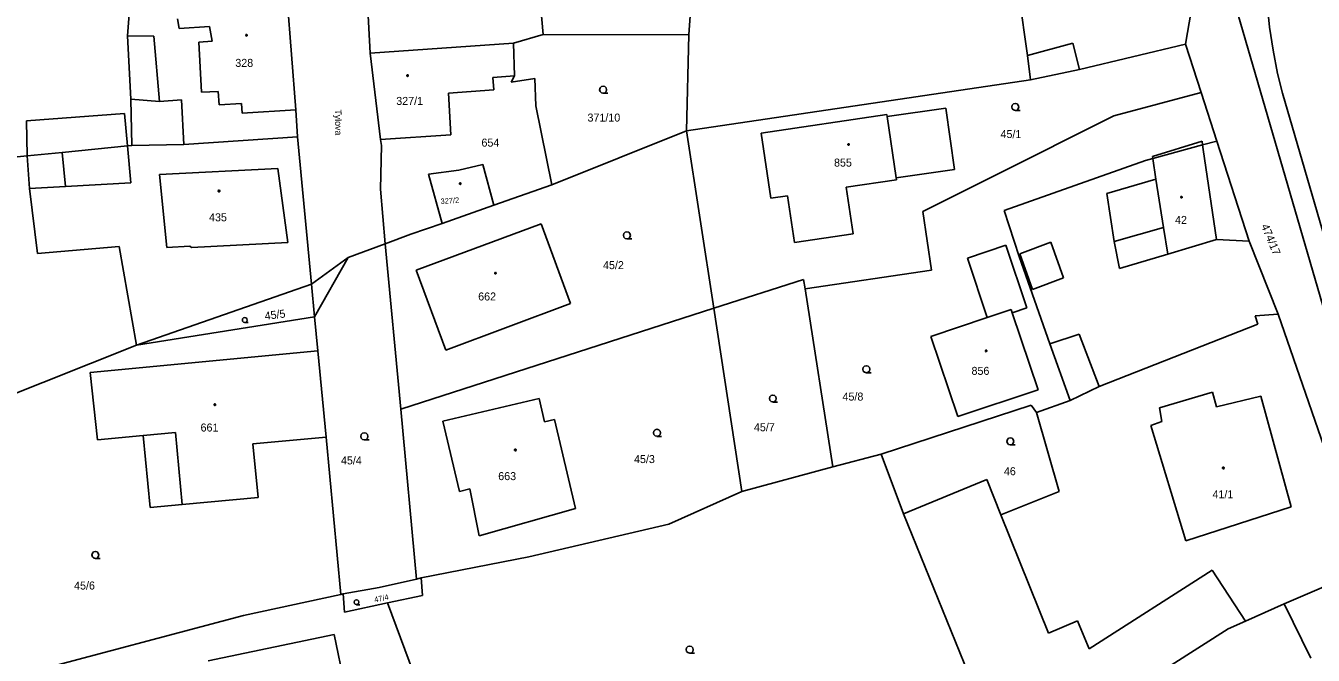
# Model space of a CAD drawing. Extents: x -757994 to -755874, y -1047691 to -1046119.
# Drawn here: x -757584.9 to -757448.1, y -1046980.7 to -1046913.8 of the extents above; entities that cross this region are included whole.
import ezdxf

# ---------------------------------------------------------------- set-up
doc = ezdxf.new("R2010")
doc.units = 0
doc.layers.add('katastrální mapa', color=7, linetype='Continuous')

msp = doc.modelspace()

# ---------------------------------------------------------------- linework, layer by layer
at = {"layer": 'katastrální mapa'}
for p, q in [((-757478.46, -1046916.96), (-757481.16, -1046897.98)), ((-757548.94, -1046903.57), (-757548.29, -1046916.7)), ((-757529.91, -1046914.73), (-757530.85, -1046904.01)), ((-757514.43, -1046914.75), (-757513.9, -1046906.58)), ((-757556.16, -1046922.73), (-757557.11, -1046910.95)), ((-757573.81, -1046911.65), (-757574.05, -1046914.86)), ((-757461.69, -1046915.73), (-757461.11, -1046912.25)), ((-757456.38, -1046911.66), (-757436.98, -1046978.47)), ((-757568.73, -1046913.04), (-757568.55, -1046914.08)), ((-757568.55, -1046914.08), (-757565.34, -1046913.88)), ((-757565.34, -1046913.88), (-757565.06, -1046915.43)), ((-757574.05, -1046914.86), (-757573.7, -1046921.6)), ((-757571.25, -1046914.89), (-757574.05, -1046914.86)), ((-757570.66, -1046921.83), (-757571.25, -1046914.89)), ((-757565.06, -1046915.43), (-757566.49, -1046915.53)), ((-757566.49, -1046915.53), (-757566.18, -1046920.86)), ((-757533.05, -1046915.64), (-757529.91, -1046914.73)), ((-757514.43, -1046914.75), (-757529.91, -1046914.73)), ((-757514.69, -1046924.95), (-757514.43, -1046914.75)), ((-757473.66, -1046915.63), (-757478.46, -1046916.96)), ((-757472.94, -1046918.43), (-757473.66, -1046915.63)), ((-757548.29, -1046916.7), (-757533.05, -1046915.64)), ((-757548.29, -1046916.7), (-757547.17, -1046925.88)), ((-757532.96, -1046919.12), (-757533.05, -1046915.64)), ((-757478.17, -1046919.55), (-757478.46, -1046916.96)), ((-757472.94, -1046918.43), (-757461.69, -1046915.73)), ((-757460.02, -1046920.89), (-757461.69, -1046915.73)), ((-757535.24, -1046919.29), (-757532.96, -1046919.12)), ((-757535.14, -1046920.58), (-757535.24, -1046919.29)), ((-757532.96, -1046919.12), (-757533.3, -1046919.8)), ((-757530.8, -1046919.4), (-757533.3, -1046919.8)), ((-757530.7, -1046922.3), (-757530.8, -1046919.4)), ((-757514.69, -1046924.95), (-757478.17, -1046919.55)), ((-757478.17, -1046919.55), (-757472.94, -1046918.43)), ((-757566.18, -1046920.86), (-757564.42, -1046920.76)), ((-757564.42, -1046920.76), (-757564.33, -1046922.2)), ((-757539.95, -1046920.96), (-757535.14, -1046920.58)), ((-757539.71, -1046925.36), (-757539.95, -1046920.96)), ((-757469.29, -1046923.35), (-757460.02, -1046920.89)), ((-757458.36, -1046926.04), (-757460.02, -1046920.89)), ((-757451.4, -1046920.95), (-757445.34, -1046941.72)), ((-757573.7, -1046921.6), (-757573.58, -1046926.51)), ((-757570.66, -1046921.83), (-757573.7, -1046921.6)), ((-757568.3, -1046921.65), (-757570.66, -1046921.83)), ((-757568.05, -1046926.41), (-757568.3, -1046921.65)), ((-757564.33, -1046922.2), (-757561.94, -1046922.06)), ((-757561.94, -1046922.06), (-757561.88, -1046923.07)), ((-757529, -1046930.7), (-757530.7, -1046922.3)), ((-757584.79, -1046923.88), (-757574.38, -1046923.1)), ((-757574.38, -1046923.1), (-757574.05, -1046926.56)), ((-757561.88, -1046923.07), (-757556.16, -1046922.73)), ((-757555.99, -1046925.6), (-757556.16, -1046922.73)), ((-757506.76, -1046925.19), (-757493.41, -1046923.22)), ((-757493.41, -1046923.22), (-757493.38, -1046923.42)), ((-757493.38, -1046923.42), (-757487.14, -1046922.54)), ((-757492.41, -1046929.96), (-757493.38, -1046923.42)), ((-757487.14, -1046922.54), (-757486.22, -1046929.05)), ((-757482.1, -1046929.77), (-757469.29, -1046923.35)), ((-757584.72, -1046927.61), (-757584.79, -1046923.88)), ((-757529, -1046930.7), (-757514.69, -1046924.95)), ((-757514.69, -1046924.95), (-757511.78, -1046943.8)), ((-757505.74, -1046932.11), (-757506.76, -1046925.19)), ((-757580.99, -1046927.24), (-757574.05, -1046926.56)), ((-757574.05, -1046926.56), (-757573.58, -1046926.51)), ((-757574.05, -1046926.56), (-757573.68, -1046930.47)), ((-757573.58, -1046926.51), (-757568.05, -1046926.41)), ((-757568.05, -1046926.41), (-757555.99, -1046925.6)), ((-757554.51, -1046941.24), (-757555.99, -1046925.6)), ((-757547.17, -1046925.88), (-757539.71, -1046925.36)), ((-757547.17, -1046925.88), (-757547.09, -1046926.5)), ((-757547.09, -1046926.5), (-757547.17, -1046931.13)), ((-757465.21, -1046927.68), (-757459.94, -1046926.04)), ((-757459.88, -1046926.45), (-757465.18, -1046927.9)), ((-757459.88, -1046926.45), (-757459.94, -1046926.04)), ((-757458.36, -1046926.04), (-757459.88, -1046926.45)), ((-757459.81, -1046926.93), (-757459.88, -1046926.45)), ((-757454.92, -1046936.66), (-757458.36, -1046926.04)), ((-757603.26, -1046929.43), (-757584.72, -1046927.61)), ((-757584.72, -1046927.61), (-757580.99, -1046927.24)), ((-757584.45, -1046931.08), (-757584.72, -1046927.61)), ((-757580.64, -1046930.86), (-757580.99, -1046927.24)), ((-757465.18, -1046927.9), (-757465.94, -1046928.11)), ((-757465.18, -1046927.9), (-757465.21, -1046927.68)), ((-757464.85, -1046930.08), (-757465.18, -1046927.9)), ((-757458.4, -1046936.49), (-757459.81, -1046926.93)), ((-757570.65, -1046929.59), (-757558.07, -1046928.94)), ((-757558.07, -1046928.94), (-757557.02, -1046936.81)), ((-757542.08, -1046929.56), (-757538.86, -1046929.13)), ((-757538.86, -1046929.13), (-757536.33, -1046928.52)), ((-757536.33, -1046928.52), (-757535.15, -1046932.85)), ((-757486.22, -1046929.05), (-757492.41, -1046929.96)), ((-757465.94, -1046928.11), (-757480.97, -1046933.4)), ((-757573.68, -1046930.47), (-757580.64, -1046930.86)), ((-757569.89, -1046937.33), (-757570.65, -1046929.59)), ((-757540.65, -1046934.78), (-757542.08, -1046929.56)), ((-757492.38, -1046930.16), (-757497.72, -1046930.94)), ((-757492.41, -1046929.96), (-757492.38, -1046930.16)), ((-757489.58, -1046933.52), (-757482.1, -1046929.77)), ((-757470.06, -1046931.62), (-757464.85, -1046930.08)), ((-757464.03, -1046935.23), (-757464.85, -1046930.08)), ((-757580.64, -1046930.86), (-757584.45, -1046931.08)), ((-757583.62, -1046937.99), (-757584.45, -1046931.08)), ((-757547.17, -1046931.13), (-757546.67, -1046936.95)), ((-757535.15, -1046932.85), (-757529, -1046930.7)), ((-757503.95, -1046931.85), (-757505.74, -1046932.11)), ((-757503.21, -1046936.8), (-757503.95, -1046931.85)), ((-757497.72, -1046930.94), (-757497, -1046935.89)), ((-757469.26, -1046936.72), (-757470.06, -1046931.62)), ((-757535.15, -1046932.85), (-757540.65, -1046934.78)), ((-757480.97, -1046933.4), (-757479.37, -1046938.3)), ((-757488.66, -1046939.74), (-757489.58, -1046933.52)), ((-757546.67, -1046936.95), (-757543.97, -1046935.94)), ((-757540.65, -1046934.78), (-757543.97, -1046935.94)), ((-757530.11, -1046934.84), (-757543.39, -1046939.74)), ((-757530.11, -1046934.84), (-757526.99, -1046943.3)), ((-757497, -1046935.89), (-757503.21, -1046936.8)), ((-757464.03, -1046935.23), (-757469.26, -1046936.72)), ((-757463.58, -1046938.05), (-757464.03, -1046935.23)), ((-757574.93, -1046937.25), (-757583.62, -1046937.99)), ((-757573.1, -1046947.7), (-757574.93, -1046937.25)), ((-757567.44, -1046937.19), (-757569.89, -1046937.33)), ((-757567.24, -1046937.36), (-757567.44, -1046937.19)), ((-757557.02, -1046936.81), (-757567.24, -1046937.36)), ((-757550.6, -1046938.42), (-757546.67, -1046936.95)), ((-757546.67, -1046936.95), (-757545.03, -1046954.51)), ((-757480.78, -1046937.08), (-757484.86, -1046938.46)), ((-757478.56, -1046943.75), (-757480.78, -1046937.08)), ((-757479.3, -1046938.03), (-757475.99, -1046936.79)), ((-757475.99, -1046936.79), (-757474.66, -1046940.56)), ((-757469.26, -1046936.72), (-757468.72, -1046939.58)), ((-757458.4, -1046936.49), (-757463.58, -1046938.05)), ((-757454.92, -1046936.66), (-757458.4, -1046936.49)), ((-757451.87, -1046944.44), (-757454.92, -1046936.66)), ((-757554.51, -1046941.24), (-757550.6, -1046938.42)), ((-757554.18, -1046944.69), (-757550.6, -1046938.42)), ((-757484.86, -1046938.46), (-757482.76, -1046944.78)), ((-757476.12, -1046947.58), (-757479.37, -1046938.3)), ((-757477.93, -1046941.81), (-757479.3, -1046938.03)), ((-757468.72, -1046939.58), (-757463.58, -1046938.05)), ((-757543.39, -1046939.74), (-757540.26, -1046948.23)), ((-757502.1, -1046941.73), (-757488.66, -1046939.74)), ((-757573.1, -1046947.7), (-757554.51, -1046941.24)), ((-757554.18, -1046944.69), (-757554.51, -1046941.24)), ((-757511.78, -1046943.8), (-757502.25, -1046940.74)), ((-757502.25, -1046940.74), (-757502.1, -1046941.73)), ((-757474.66, -1046940.56), (-757477.93, -1046941.81)), ((-757502.1, -1046941.73), (-757499.15, -1046960.65)), ((-757511.78, -1046943.8), (-757545.03, -1046954.51)), ((-757526.99, -1046943.3), (-757540.26, -1046948.23)), ((-757511.78, -1046943.8), (-757508.8, -1046963.25)), ((-757482.76, -1046944.78), (-757480.22, -1046943.92)), ((-757480.22, -1046943.92), (-757480.1, -1046944.27)), ((-757480.1, -1046944.27), (-757478.56, -1046943.75)), ((-757477.35, -1046952.47), (-757480.1, -1046944.27)), ((-757573.1, -1046947.7), (-757554.18, -1046944.69)), ((-757553.84, -1046948.32), (-757554.18, -1046944.69)), ((-757482.76, -1046944.78), (-757488.74, -1046946.79)), ((-757470.85, -1046952.11), (-757454.02, -1046945.48)), ((-757454.29, -1046944.59), (-757451.87, -1046944.44)), ((-757454.02, -1046945.48), (-757454.29, -1046944.59)), ((-757442.52, -1046971.47), (-757451.87, -1046944.44)), ((-757488.74, -1046946.79), (-757485.89, -1046955.3)), ((-757476.12, -1046947.58), (-757472.98, -1046946.55)), ((-757472.98, -1046946.55), (-757470.85, -1046952.11)), ((-757593.1, -1046955.71), (-757573.1, -1046947.7)), ((-757578.03, -1046950.61), (-757553.84, -1046948.32)), ((-757553.84, -1046948.32), (-757552.97, -1046957.47)), ((-757476.12, -1046947.58), (-757473.93, -1046953.59)), ((-757577.24, -1046957.77), (-757578.03, -1046950.61)), ((-757485.89, -1046955.3), (-757477.35, -1046952.47)), ((-757473.93, -1046953.59), (-757470.85, -1046952.11)), ((-757540.56, -1046955.78), (-757530.33, -1046953.37)), ((-757530.33, -1046953.37), (-757529.75, -1046955.85)), ((-757477.52, -1046954.87), (-757473.93, -1046953.59)), ((-757464.44, -1046954.36), (-757458.82, -1046952.7)), ((-757458.82, -1046952.7), (-757458.39, -1046954.25)), ((-757458.39, -1046954.25), (-757453.68, -1046953.15)), ((-757453.68, -1046953.15), (-757450.48, -1046964.9)), ((-757545.03, -1046954.51), (-757543.35, -1046972.58)), ((-757494.03, -1046959.28), (-757478.08, -1046954.08)), ((-757478.08, -1046954.08), (-757477.52, -1046954.87)), ((-757475.11, -1046963.25), (-757477.52, -1046954.87)), ((-757464.2, -1046955.84), (-757464.44, -1046954.36)), ((-757538.8, -1046963.25), (-757540.56, -1046955.78)), ((-757529.75, -1046955.85), (-757528.71, -1046955.6)), ((-757528.71, -1046955.6), (-757526.48, -1046965.07)), ((-757465.39, -1046956.26), (-757464.2, -1046955.84)), ((-757461.66, -1046968.48), (-757465.39, -1046956.26)), ((-757572.37, -1046957.31), (-757577.24, -1046957.77)), ((-757568.97, -1046956.99), (-757572.37, -1046957.31)), ((-757571.64, -1046964.97), (-757572.37, -1046957.31)), ((-757568.24, -1046964.65), (-757568.97, -1046956.99)), ((-757552.97, -1046957.47), (-757560.73, -1046958.21)), ((-757551.38, -1046974.2), (-757552.97, -1046957.47)), ((-757560.73, -1046958.21), (-757560.19, -1046963.89)), ((-757499.15, -1046960.65), (-757494.03, -1046959.28)), ((-757494.03, -1046959.28), (-757491.65, -1046965.63)), ((-757508.8, -1046963.25), (-757499.15, -1046960.65)), ((-757491.65, -1046965.63), (-757482.8, -1046961.99)), ((-757482.8, -1046961.99), (-757481.29, -1046965.74)), ((-757537.68, -1046962.99), (-757538.8, -1046963.25)), ((-757536.69, -1046967.98), (-757537.68, -1046962.99)), ((-757516.56, -1046966.71), (-757508.8, -1046963.25)), ((-757481.29, -1046965.74), (-757475.11, -1046963.25)), ((-757568.24, -1046964.65), (-757571.64, -1046964.97)), ((-757560.19, -1046963.89), (-757568.24, -1046964.65)), ((-757526.48, -1046965.07), (-757536.69, -1046967.98)), ((-757483.8, -1046984.92), (-757491.65, -1046965.63)), ((-757481.29, -1046965.74), (-757476.24, -1046978.29)), ((-757450.48, -1046964.9), (-757461.66, -1046968.48)), ((-757531.44, -1046970.18), (-757516.56, -1046966.71)), ((-757542.87, -1046972.41), (-757531.44, -1046970.18)), ((-757471.92, -1046979.98), (-757458.87, -1046971.63)), ((-757458.87, -1046971.63), (-757455.34, -1046977.02)), ((-757451.22, -1046975.19), (-757442.52, -1046971.47)), ((-757547.33, -1046973.46), (-757543.35, -1046972.58)), ((-757543.35, -1046972.58), (-757542.87, -1046972.41)), ((-757542.73, -1046974.31), (-757542.87, -1046972.41)), ((-757561.73, -1046976.43), (-757551.38, -1046974.2)), ((-757551.38, -1046974.2), (-757551.13, -1046974.13)), ((-757551.13, -1046974.13), (-757547.33, -1046973.46)), ((-757551.13, -1046974.13), (-757551.01, -1046976.07)), ((-757546.44, -1046975.08), (-757542.73, -1046974.31)), ((-757551.01, -1046976.07), (-757546.44, -1046975.08)), ((-757546.44, -1046975.08), (-757535.91, -1047003.44)), ((-757455.34, -1046977.02), (-757451.22, -1046975.19)), ((-757451.22, -1046975.19), (-757448.38, -1046980.96)), ((-757584.92, -1046982.6), (-757561.73, -1046976.43)), ((-757476.24, -1046978.29), (-757473.15, -1046977.01)), ((-757473.15, -1046977.01), (-757471.92, -1046979.98)), ((-757455.34, -1046977.02), (-757457.17, -1046977.83)), ((-757552.1, -1046978.43), (-757565.48, -1046981.25)), ((-757549.65, -1046990.2), (-757552.1, -1046978.43)), ((-757468.67, -1046985.16), (-757457.17, -1046977.83))]:
    msp.add_line(p, q, dxfattribs=at)
for points in [[(-757451.4, -1046920.95), (-757451.91, -1046918.86), (-757452.39, -1046916.4), (-757452.77, -1046913.93), (-757453.04, -1046911.44), (-757453.2, -1046908.94), (-757453.25, -1046906.44), (-757453.19, -1046903.94), (-757453.05, -1046901.79), (-757452.85, -1046899.75), (-757452.54, -1046897.48), (-757452.14, -1046895.22), (-757451.64, -1046892.98), (-757451.06, -1046890.76), (-757450.39, -1046888.56), (-757449.63, -1046886.39), (-757448.88, -1046884.49)], [(-757523.54, -1046920.95), (-757523.73, -1046920.9), (-757523.86, -1046920.76), (-757523.92, -1046920.58), (-757523.86, -1046920.4), (-757523.73, -1046920.26), (-757523.55, -1046920.21), (-757523.36, -1046920.26), (-757523.23, -1046920.4), (-757523.18, -1046920.59), (-757523.23, -1046920.77), (-757523.36, -1046920.91), (-757523.55, -1046920.96), (-757523.05, -1046920.96)], [(-757479.76, -1046922.78), (-757479.95, -1046922.73), (-757480.09, -1046922.6), (-757480.14, -1046922.41), (-757480.09, -1046922.23), (-757479.95, -1046922.09), (-757479.77, -1046922.04), (-757479.58, -1046922.09), (-757479.45, -1046922.23), (-757479.4, -1046922.42), (-757479.45, -1046922.61), (-757479.58, -1046922.74), (-757479.77, -1046922.79), (-757479.27, -1046922.79)], [(-757521, -1046936.42), (-757521.19, -1046936.37), (-757521.33, -1046936.24), (-757521.38, -1046936.05), (-757521.33, -1046935.87), (-757521.19, -1046935.73), (-757521.01, -1046935.68), (-757520.82, -1046935.73), (-757520.69, -1046935.87), (-757520.64, -1046936.06), (-757520.69, -1046936.25), (-757520.82, -1046936.38), (-757521.01, -1046936.43), (-757520.51, -1046936.43)], [(-757561.59, -1046945.31), (-757561.72, -1046945.28), (-757561.82, -1046945.18), (-757561.85, -1046945.05), (-757561.82, -1046944.92), (-757561.72, -1046944.83), (-757561.59, -1046944.79), (-757561.46, -1046944.83), (-757561.37, -1046944.92), (-757561.33, -1046945.05), (-757561.37, -1046945.19), (-757561.46, -1046945.28), (-757561.6, -1046945.32), (-757561.25, -1046945.32)], [(-757495.58, -1046950.64), (-757495.77, -1046950.59), (-757495.91, -1046950.46), (-757495.96, -1046950.27), (-757495.91, -1046950.09), (-757495.77, -1046949.95), (-757495.59, -1046949.9), (-757495.4, -1046949.95), (-757495.26, -1046950.09), (-757495.22, -1046950.28), (-757495.26, -1046950.47), (-757495.4, -1046950.6), (-757495.59, -1046950.65), (-757495.09, -1046950.65)], [(-757505.51, -1046953.75), (-757505.7, -1046953.7), (-757505.84, -1046953.57), (-757505.89, -1046953.38), (-757505.84, -1046953.2), (-757505.7, -1046953.06), (-757505.52, -1046953.01), (-757505.33, -1046953.06), (-757505.2, -1046953.2), (-757505.15, -1046953.39), (-757505.2, -1046953.58), (-757505.33, -1046953.71), (-757505.52, -1046953.76), (-757505.02, -1046953.76)], [(-757548.89, -1046957.77), (-757549.08, -1046957.72), (-757549.22, -1046957.59), (-757549.27, -1046957.4), (-757549.22, -1046957.22), (-757549.08, -1046957.08), (-757548.9, -1046957.03), (-757548.71, -1046957.08), (-757548.58, -1046957.22), (-757548.53, -1046957.41), (-757548.58, -1046957.6), (-757548.71, -1046957.73), (-757548.9, -1046957.78), (-757548.4, -1046957.78)], [(-757517.82, -1046957.39), (-757518.01, -1046957.34), (-757518.15, -1046957.21), (-757518.2, -1046957.02), (-757518.15, -1046956.84), (-757518.01, -1046956.7), (-757517.83, -1046956.65), (-757517.64, -1046956.7), (-757517.5, -1046956.84), (-757517.46, -1046957.03), (-757517.5, -1046957.22), (-757517.64, -1046957.35), (-757517.83, -1046957.4), (-757517.33, -1046957.4)], [(-757480.29, -1046958.3), (-757480.48, -1046958.25), (-757480.61, -1046958.12), (-757480.67, -1046957.93), (-757480.61, -1046957.75), (-757480.48, -1046957.61), (-757480.3, -1046957.56), (-757480.11, -1046957.61), (-757479.98, -1046957.75), (-757479.93, -1046957.94), (-757479.98, -1046958.12), (-757480.11, -1046958.26), (-757480.3, -1046958.31), (-757479.8, -1046958.31)], [(-757577.46, -1046970.37), (-757577.65, -1046970.32), (-757577.78, -1046970.19), (-757577.84, -1046970), (-757577.78, -1046969.82), (-757577.65, -1046969.68), (-757577.47, -1046969.63), (-757577.28, -1046969.68), (-757577.15, -1046969.82), (-757577.1, -1046970.01), (-757577.15, -1046970.2), (-757577.28, -1046970.33), (-757577.47, -1046970.38), (-757576.97, -1046970.38)], [(-757549.73, -1046975.27), (-757549.86, -1046975.24), (-757549.96, -1046975.14), (-757549.99, -1046975.01), (-757549.96, -1046974.88), (-757549.86, -1046974.79), (-757549.73, -1046974.75), (-757549.6, -1046974.79), (-757549.51, -1046974.88), (-757549.47, -1046975.01), (-757549.51, -1046975.15), (-757549.6, -1046975.24), (-757549.74, -1046975.28), (-757549.39, -1046975.28)], [(-757514.34, -1046980.42), (-757514.53, -1046980.37), (-757514.67, -1046980.24), (-757514.72, -1046980.05), (-757514.67, -1046979.87), (-757514.53, -1046979.73), (-757514.35, -1046979.68), (-757514.16, -1046979.73), (-757514.02, -1046979.87), (-757513.98, -1046980.06), (-757514.02, -1046980.25), (-757514.16, -1046980.38), (-757514.35, -1046980.43), (-757513.85, -1046980.43)]]:
    msp.add_lwpolyline(points, dxfattribs=at)
for points in [[(-757561.42, -1046914.72), (-757561.37, -1046914.73), (-757561.35, -1046914.77), (-757561.34, -1046914.8), (-757561.35, -1046914.85), (-757561.39, -1046914.88), (-757561.42, -1046914.89), (-757561.47, -1046914.87), (-757561.5, -1046914.84), (-757561.51, -1046914.8), (-757561.5, -1046914.76), (-757561.46, -1046914.72)], [(-757544.31, -1046919), (-757544.26, -1046919.01), (-757544.24, -1046919.06), (-757544.23, -1046919.09), (-757544.24, -1046919.14), (-757544.28, -1046919.17), (-757544.31, -1046919.18), (-757544.35, -1046919.16), (-757544.39, -1046919.13), (-757544.4, -1046919.09), (-757544.39, -1046919.04), (-757544.35, -1046919.01)], [(-757497.48, -1046926.32), (-757497.43, -1046926.33), (-757497.41, -1046926.37), (-757497.4, -1046926.4), (-757497.41, -1046926.45), (-757497.45, -1046926.48), (-757497.48, -1046926.49), (-757497.52, -1046926.47), (-757497.55, -1046926.44), (-757497.57, -1046926.4), (-757497.55, -1046926.36), (-757497.51, -1046926.32)], [(-757538.72, -1046930.48), (-757538.67, -1046930.49), (-757538.65, -1046930.53), (-757538.64, -1046930.56), (-757538.65, -1046930.61), (-757538.69, -1046930.64), (-757538.72, -1046930.65), (-757538.76, -1046930.63), (-757538.79, -1046930.6), (-757538.8, -1046930.56), (-757538.79, -1046930.52), (-757538.75, -1046930.48)], [(-757564.33, -1046931.26), (-757564.28, -1046931.27), (-757564.25, -1046931.32), (-757564.24, -1046931.35), (-757564.25, -1046931.4), (-757564.29, -1046931.43), (-757564.33, -1046931.44), (-757564.38, -1046931.42), (-757564.41, -1046931.39), (-757564.42, -1046931.35), (-757564.41, -1046931.3), (-757564.36, -1046931.27)], [(-757462.12, -1046931.92), (-757462.07, -1046931.93), (-757462.04, -1046931.97), (-757462.03, -1046932), (-757462.04, -1046932.04), (-757462.09, -1046932.08), (-757462.12, -1046932.09), (-757462.17, -1046932.07), (-757462.2, -1046932.04), (-757462.21, -1046932), (-757462.2, -1046931.96), (-757462.16, -1046931.92)], [(-757534.98, -1046939.98), (-757534.93, -1046939.99), (-757534.91, -1046940.04), (-757534.9, -1046940.07), (-757534.91, -1046940.12), (-757534.95, -1046940.15), (-757534.98, -1046940.16), (-757535.02, -1046940.14), (-757535.05, -1046940.11), (-757535.07, -1046940.07), (-757535.05, -1046940.02), (-757535.01, -1046939.99)], [(-757482.87, -1046948.23), (-757482.82, -1046948.24), (-757482.79, -1046948.29), (-757482.78, -1046948.32), (-757482.79, -1046948.37), (-757482.84, -1046948.4), (-757482.87, -1046948.41), (-757482.92, -1046948.39), (-757482.95, -1046948.36), (-757482.96, -1046948.32), (-757482.95, -1046948.27), (-757482.91, -1046948.24)], [(-757564.77, -1046953.96), (-757564.72, -1046953.97), (-757564.7, -1046954.01), (-757564.69, -1046954.04), (-757564.7, -1046954.09), (-757564.74, -1046954.12), (-757564.77, -1046954.12), (-757564.82, -1046954.11), (-757564.85, -1046954.08), (-757564.85, -1046954.04), (-757564.85, -1046954), (-757564.8, -1046953.96)], [(-757532.87, -1046958.76), (-757532.82, -1046958.77), (-757532.79, -1046958.82), (-757532.78, -1046958.85), (-757532.79, -1046958.9), (-757532.84, -1046958.93), (-757532.87, -1046958.94), (-757532.92, -1046958.92), (-757532.95, -1046958.89), (-757532.96, -1046958.85), (-757532.95, -1046958.8), (-757532.91, -1046958.77)], [(-757457.68, -1046960.68), (-757457.63, -1046960.69), (-757457.6, -1046960.73), (-757457.6, -1046960.76), (-757457.6, -1046960.8), (-757457.65, -1046960.84), (-757457.68, -1046960.85), (-757457.73, -1046960.83), (-757457.76, -1046960.8), (-757457.77, -1046960.76), (-757457.76, -1046960.72), (-757457.72, -1046960.68)]]:
    msp.add_lwpolyline(points, close=True, dxfattribs=at)

# ---------------------------------------------------------------- texts
for s, p in [('328', (-757562.6, -1046918.16)), ('327/1', (-757545.51, -1046922.2)), ('371/10', (-757525.2, -1046923.97)), ('45/1', (-757481.34, -1046925.72)), ('654', (-757536.46, -1046926.63)), ('855', (-757499.02, -1046928.75)), ('435', (-757565.39, -1046934.56)), ('42', (-757462.81, -1046934.84)), ('45/2', (-757523.55, -1046939.64)), ('662', (-757536.81, -1046942.97)), ('856', (-757484.42, -1046950.87)), ('45/8', (-757498.12, -1046953.6)), ('661', (-757566.29, -1046956.89)), ('45/7', (-757507.53, -1046956.86)), ('45/3', (-757520.26, -1046960.24)), ('45/4', (-757551.38, -1046960.38)), ('46', (-757480.98, -1046961.53)), ('663', (-757534.68, -1046962.05)), ('41/1', (-757458.83, -1046963.98)), ('45/6', (-757579.72, -1046973.67))]:
    msp.add_text(s, height=0.85, dxfattribs=at).set_placement(p)
for s, height, rotation, p in [('Tylova', 0.7, 271.009, (-757552.03, -1046922.68)), ('327/2', 0.57, 3.9534, (-757540.78, -1046932.72)), ('474/17', 0.85, 292.5523, (-757453.68, -1046935.05)), ('45/5', 0.85, 7.2193, (-757559.43, -1046945.04)), ('47/4', 0.595, 12.2613, (-757547.78, -1046975.06))]:
    msp.add_text(s, height=height, rotation=rotation, dxfattribs=at).set_placement(p)

doc.saveas('drawing.dxf')
